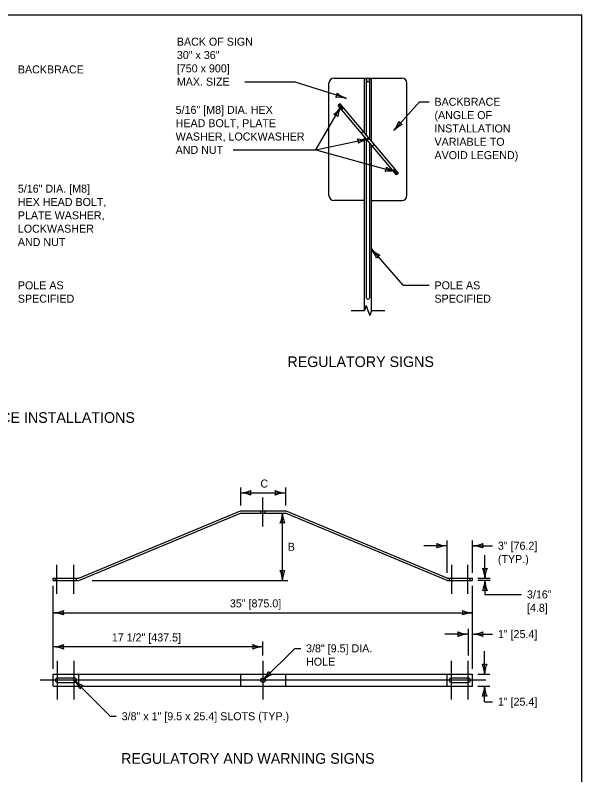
# Model space of a CAD drawing. Extents: x 49991.4 to 50021, y 49987.6 to 50011.4.
# Drawn here: x 50004.36 to 50008.61, y 50005.57 to 50011.26 of the extents above; entities that cross this region are included whole.
import ezdxf

# ---------------------------------------------------------------- set-up
doc = ezdxf.new("R2010")
doc.units = 0
for name, color, linetype in [('Level 1', 7, 'Continuous'), ('Level 2', 7, 'Continuous'), ('Level 3', 7, 'Continuous'), ('Level 4', 7, 'Continuous'), ('Level 5', 7, 'Continuous'), ('Level 6', 7, 'Continuous')]:
    doc.layers.add(name, color=color, linetype=linetype)

msp = doc.modelspace()

# ---------------------------------------------------------------- linework, layer by layer
at = {"layer": 'Level 1'}
for p, q in [((50006.7554, 50010.7907), (50007.264, 50010.7907)), ((50006.9838, 50010.7884), (50007.0356, 50010.7884)), ((50006.9838, 50010.3807), (50006.9838, 50010.7884)), ((50006.9961, 50010.7884), (50006.9961, 50010.3661)), ((50007.0231, 50010.3339), (50007.0231, 50010.7884)), ((50007.0356, 50010.319), (50007.0356, 50010.7884)), ((50006.7172, 50009.911), (50006.7172, 50010.7524)), ((50007.3023, 50009.911), (50007.3023, 50010.7524)), ((50006.8008, 50010.5988), (50006.786, 50010.5863)), ((50007.2382, 50010.0776), (50006.8008, 50010.5988)), ((50007.2232, 50010.0651), (50006.786, 50010.5863)), ((50006.7978, 50010.5827), (50006.8116, 50010.5663)), ((50006.8023, 50010.5865), (50006.816, 50010.5701)), ((50006.8274, 50010.5672), (50006.8126, 50010.5546)), ((50006.9754, 50010.3907), (50006.9605, 50010.3783)), ((50006.9838, 50009.0483), (50006.9838, 50010.3505)), ((50006.9962, 50010.3358), (50006.9962, 50009.1471)), ((50007.0232, 50009.1471), (50007.0232, 50010.3036)), ((50007.0356, 50009.0483), (50007.0356, 50010.2887)), ((50007.0583, 50010.292), (50007.0433, 50010.2795)), ((50007.2116, 50010.1092), (50007.1968, 50010.0968)), ((50007.2084, 50010.0938), (50007.2221, 50010.0774)), ((50007.2128, 50010.0975), (50007.2266, 50010.0811)), ((50007.2382, 50010.0776), (50007.2232, 50010.0651)), ((50006.9838, 50009.8727), (50006.7554, 50009.8727)), ((50007.0356, 50009.8727), (50007.264, 50009.8727)), ((50004.8399, 50007.0405), (50006.0533, 50007.546)), ((50004.8399, 50007.0236), (50006.0533, 50007.5292)), ((50006.0533, 50007.546), (50006.3903, 50007.546)), ((50006.0533, 50007.5292), (50006.3903, 50007.5292)), ((50007.6037, 50007.0405), (50006.3903, 50007.546)), ((50007.6037, 50007.0236), (50006.3903, 50007.5292)), ((50004.649, 50007.0236), (50004.649, 50007.0405)), ((50004.649, 50007.0405), (50004.8399, 50007.0405)), ((50004.649, 50007.0236), (50004.8399, 50007.0236)), ((50007.6037, 50007.0405), (50007.7947, 50007.0405)), ((50007.6037, 50007.0236), (50007.7947, 50007.0236)), ((50007.7947, 50007.0236), (50007.7947, 50007.0405)), ((50004.649, 50006.3213), (50007.7947, 50006.3213)), ((50004.649, 50006.2314), (50004.649, 50006.3213)), ((50004.8399, 50006.2314), (50004.8399, 50006.3213)), ((50006.0533, 50006.3213), (50006.0533, 50006.2314)), ((50006.3903, 50006.3213), (50006.3903, 50006.2314)), ((50007.6037, 50006.2314), (50007.6037, 50006.3213)), ((50007.7947, 50006.2314), (50007.7947, 50006.3213)), ((50004.6813, 50006.2932), (50004.8062, 50006.2932)), ((50007.6375, 50006.2933), (50007.7611, 50006.2933)), ((50004.649, 50006.2314), (50007.7947, 50006.2314)), ((50004.6813, 50006.2592), (50004.8062, 50006.2592)), ((50007.6375, 50006.2593), (50007.7611, 50006.2593))]:
    msp.add_line(p, q, dxfattribs=at)
msp.add_lwpolyline([(50008.6146, 50011.2628), (50000.3356, 50011.2628), (50000.3356, 50000.0624), (50008.6146, 50000.0624)], close=True, dxfattribs=at)
for centre, radius in [((50007.0095, 50010.7654), 0.00425), ((50007.0097, 50010.3348), 0.0051), ((50006.2218, 50006.2763), 0.0169)]:
    msp.add_circle(centre, radius, dxfattribs=at)
for centre, radius, start, end in [((50006.7554, 50010.7524), 0.0383, 90, 180), ((50007.264, 50010.7524), 0.0383, 0, 90), ((50006.8001, 50010.5846), 0.00292, 39.9351, 219.9351), ((50006.8138, 50010.5682), 0.00292, 220, 40), ((50007.2106, 50010.0957), 0.00292, 39.9351, 219.9351), ((50007.2243, 50010.0793), 0.00292, 220, 40), ((50006.7554, 50009.911), 0.0383, 180, 270), ((50007.264, 50009.911), 0.0383, 270, 360), ((50007.0097, 50009.1471), 0.0135, 180, 0.0087), ((50004.6813, 50006.2762), 0.017, 90, 270), ((50004.8062, 50006.2762), 0.017, 270, 90), ((50007.6375, 50006.2763), 0.017, 90, 270), ((50007.7611, 50006.2763), 0.017, 270, 90)]:
    msp.add_arc(centre, radius, start, end, dxfattribs=at)
at = {"layer": 'Level 3'}
for p, q in [((50006.0858, 50010.7641), (50006.4564, 50010.7641)), ((50006.846, 50010.6394), (50006.4564, 50010.7641)), ((50007.3968, 50010.6135), (50007.2068, 50010.4001)), ((50007.3968, 50010.6135), (50007.469, 50010.6135)), ((50006.6192, 50010.253), (50006.8069, 50010.5764)), ((50006.6192, 50010.253), (50007.0097, 50010.3348)), ((50005.9982, 50010.253), (50006.6192, 50010.253)), ((50006.6192, 50010.253), (50007.2175, 50010.0875)), ((50007.2732, 50009.2372), (50007.0356, 50009.5099)), ((50007.2732, 50009.2372), (50007.469, 50009.2372)), ((50006.0533, 50007.7208), (50006.0533, 50007.586)), ((50006.3903, 50007.7208), (50006.3903, 50007.586)), ((50006.0533, 50007.6808), (50006.3903, 50007.6808)), ((50006.3678, 50007.0236), (50006.3678, 50007.5292)), ((50007.6037, 50007.0805), (50007.6037, 50007.3244)), ((50007.7947, 50007.0805), (50007.7947, 50007.3244)), ((50007.6037, 50007.2844), (50007.4303, 50007.2844)), ((50007.7947, 50007.2844), (50007.9447, 50007.2844)), ((50007.8878, 50007.0405), (50007.8878, 50007.2139)), ((50004.9399, 50007.0236), (50006.4078, 50007.0236)), ((50007.8347, 50007.0405), (50007.9278, 50007.0405)), ((50007.9278, 50007.0236), (50007.8347, 50007.0236)), ((50007.8878, 50007.0236), (50007.8878, 50006.9192)), ((50004.649, 50006.3613), (50004.649, 50006.9836)), ((50007.7947, 50006.3613), (50007.7947, 50006.9836)), ((50007.8878, 50006.9192), (50008.163, 50006.9192)), ((50004.649, 50006.7821), (50007.7947, 50006.7821)), ((50007.7611, 50006.6618), (50007.7611, 50006.4613)), ((50007.7611, 50006.6218), (50007.5877, 50006.6218)), ((50007.7947, 50006.6218), (50007.9447, 50006.6218)), ((50006.2218, 50006.4613), (50006.2218, 50006.5667)), ((50006.2218, 50006.5267), (50004.649, 50006.5267)), ((50006.2218, 50006.2763), (50006.4605, 50006.515)), ((50006.4605, 50006.515), (50006.5055, 50006.515)), ((50007.8851, 50006.3213), (50007.8851, 50006.4947)), ((50007.8347, 50006.3213), (50007.9251, 50006.3213)), ((50005.0767, 50006.0059), (50004.8063, 50006.2763)), ((50007.8347, 50006.2314), (50007.9251, 50006.2314)), ((50007.8851, 50006.1151), (50007.8851, 50006.2314)), ((50007.8851, 50006.1151), (50007.9447, 50006.1151)), ((50005.0767, 50006.0059), (50005.1217, 50006.0059))]:
    msp.add_line(p, q, dxfattribs=at)
for centre, radius, start, end in [((50006.7239, 50010.6785), 0.0548, 324.3929, 0.1153), ((50006.786, 50010.4142), 0.233, 75.0814, 94.3313), ((50006.9224, 50010.8481), 0.2223, 229.7101, 249.8936), ((50006.6194, 50010.6958), 0.2223, 307.3305, 327.514), ((50007.014, 50010.4696), 0.233, 152.7018, 171.9516), ((50006.7426, 50010.4655), 0.0548, 42.0133, 77.7356), ((50007.0225, 50010.5434), 0.233, 321.1427, 340.3926), ((50007.3638, 50010.2427), 0.2223, 115.7714, 135.9549), ((50007.2892, 50010.493), 0.0548, 210.4542, 246.1766), ((50006.9731, 50010.5541), 0.2223, 259.297, 279.4805), ((50006.8842, 50010.3085), 0.0548, 353.9798, 29.7022), ((50007.0687, 50010.1094), 0.233, 104.6683, 123.9182), ((50007.0939, 50010.1217), 0.0548, 326.6751, 2.3974), ((50007.1665, 50009.8601), 0.233, 77.3636, 96.6134), ((50007.2855, 50010.2991), 0.2223, 231.9923, 252.1758), ((50006.8621, 50009.3709), 0.2223, 18.5212, 38.7047), ((50007.2035, 50009.6714), 0.233, 223.8925, 243.1424), ((50007.1198, 50009.4132), 0.0548, 113.204, 148.9264), ((50006.0418, 50007.9135), 0.233, 272.8273, 292.0772), ((50006.1815, 50007.6808), 0.0548, 162.1388, 197.8612), ((50006.3995, 50007.9029), 0.2223, 247.456, 267.6395), ((50006.2621, 50007.6808), 0.0548, 342.1388, 17.8612), ((50006.0441, 50007.4587), 0.2223, 67.456, 87.6395), ((50006.4018, 50007.4481), 0.233, 92.8273, 112.0772), ((50006.1457, 50007.5384), 0.2223, 337.456, 357.6395), ((50006.6005, 50007.5407), 0.233, 182.8273, 202.0772), ((50006.3678, 50007.401), 0.0548, 72.1388, 107.8612), ((50007.6129, 50007.5065), 0.2223, 247.456, 267.6395), ((50007.4755, 50007.2844), 0.0548, 342.1388, 17.8612), ((50007.7832, 50007.5171), 0.233, 272.8273, 292.0772), ((50007.9229, 50007.2844), 0.0548, 162.1388, 197.8612), ((50007.6152, 50007.0517), 0.233, 92.8273, 112.0772), ((50007.7855, 50007.0623), 0.2223, 67.456, 87.6395), ((50007.8878, 50007.1687), 0.0548, 252.1388, 287.8612), ((50007.6551, 50007.029), 0.233, 2.8273, 22.0772), ((50008.1099, 50007.0313), 0.2223, 157.456, 177.6395), ((50006.3678, 50007.1518), 0.0548, 252.1388, 287.8612), ((50006.1351, 50007.0121), 0.233, 2.8273, 22.0772), ((50006.5899, 50007.0144), 0.2223, 157.456, 177.6395), ((50007.6657, 50007.0328), 0.2223, 337.456, 357.6395), ((50008.1205, 50007.0351), 0.233, 182.8273, 202.0772), ((50007.8878, 50006.8954), 0.0548, 72.1388, 107.8612), ((50004.6375, 50007.0148), 0.233, 272.8273, 292.0772), ((50004.6398, 50006.56), 0.2223, 67.456, 87.6395), ((50004.7772, 50006.7821), 0.0548, 162.1388, 197.8612), ((50007.8039, 50007.0042), 0.2223, 247.456, 267.6395), ((50007.6665, 50006.7821), 0.0548, 342.1388, 17.8612), ((50007.8062, 50006.5494), 0.233, 92.8273, 112.0772), ((50007.7703, 50006.844), 0.2223, 247.456, 267.6395), ((50007.6329, 50006.6218), 0.0548, 342.1388, 17.8612), ((50007.7726, 50006.3891), 0.233, 92.8273, 112.0772), ((50007.7832, 50006.8546), 0.233, 272.8273, 292.0772), ((50007.7855, 50006.3997), 0.2223, 67.456, 87.6395), ((50007.9229, 50006.6218), 0.0548, 162.1388, 197.8612), ((50004.6375, 50006.7594), 0.233, 272.8273, 292.0772), ((50004.6398, 50006.3046), 0.2223, 67.456, 87.6395), ((50004.7772, 50006.5267), 0.0548, 162.1388, 197.8612), ((50006.231, 50006.7488), 0.2223, 247.456, 267.6395), ((50006.0936, 50006.5267), 0.0548, 342.1388, 17.8612), ((50006.2333, 50006.294), 0.233, 92.8273, 112.0772), ((50007.8851, 50006.4495), 0.0548, 252.1388, 287.8612), ((50007.6524, 50006.3098), 0.233, 2.8273, 22.0772), ((50008.1072, 50006.3121), 0.2223, 157.456, 177.6395), ((50006.0491, 50006.4327), 0.233, 317.8273, 337.0772), ((50006.3724, 50006.1128), 0.2223, 112.456, 132.6395), ((50006.3125, 50006.367), 0.0548, 207.1388, 242.8612), ((50004.6428, 50006.1257), 0.2223, 22.456, 42.6395), ((50004.9627, 50006.449), 0.233, 227.8273, 247.0772), ((50004.897, 50006.1856), 0.0548, 117.1388, 152.8612), ((50007.663, 50006.2406), 0.2223, 337.456, 357.6395), ((50008.1178, 50006.2429), 0.233, 182.8273, 202.0772), ((50007.8851, 50006.1032), 0.0548, 72.1388, 107.8612)]:
    msp.add_arc(centre, radius, start, end, dxfattribs=at)
at = {"layer": 'Level 4'}
for p, q in [((50006.2049, 50007.5292), (50006.2049, 50007.546)), ((50006.2387, 50007.5292), (50006.2387, 50007.546)), ((50004.6658, 50007.0236), (50004.6658, 50007.0405)), ((50004.8231, 50007.0236), (50004.8231, 50007.0405)), ((50007.6206, 50007.0236), (50007.6206, 50007.0405)), ((50007.7779, 50007.0236), (50007.7779, 50007.0405))]:
    msp.add_line(p, q, dxfattribs=at)
at = {"layer": 'Level 5'}
for p, q in [((50006.2218, 50007.4292), (50006.2218, 50007.646)), ((50004.6765, 50006.9236), (50004.6765, 50007.1405)), ((50004.8019, 50006.9236), (50004.8019, 50007.1405)), ((50007.6395, 50006.9236), (50007.6395, 50007.1405)), ((50007.7605, 50006.9236), (50007.7605, 50007.1405)), ((50004.6813, 50006.1314), (50004.6813, 50006.4213)), ((50004.8062, 50006.1314), (50004.8062, 50006.4213)), ((50006.2218, 50006.4213), (50006.2218, 50006.1314)), ((50007.6375, 50006.1314), (50007.6375, 50006.4213)), ((50007.7611, 50006.1314), (50007.7611, 50006.4213)), ((50007.8947, 50006.2763), (50004.549, 50006.2763))]:
    msp.add_line(p, q, dxfattribs=at)
at = {"layer": 'Level 6'}
for p, q in [((50006.9967, 50009.0849), (50006.9838, 50009.0483)), ((50006.9967, 50009.0849), (50007.0097, 50009.0483)), ((50006.8838, 50009.0483), (50006.9838, 50009.0483)), ((50007.0097, 50009.0483), (50007.0227, 50009.0117)), ((50007.0356, 50009.0483), (50007.0227, 50009.0117)), ((50007.0356, 50009.0483), (50007.1356, 50009.0483))]:
    msp.add_line(p, q, dxfattribs=at)

# ---------------------------------------------------------------- texts
at = {"layer": 'Level 2'}
for s, height, p in [('BACK OF SIGN', 0.06, (50005.5758, 50011.0341)), ('30" x 36"', 0.06, (50005.5758, 50010.9341)), ('BACKBRACE', 0.06, (50004.3827, 50010.8263)), ('[750 x 900]', 0.06, (50005.5758, 50010.8341)), ('MAX. SIZE', 0.06, (50005.5758, 50010.7341)), ('BACKBRACE', 0.06, (50007.509, 50010.5835)), ('5/16" [M8] DIA. HEX', 0.06, (50005.5668, 50010.523)), ('(ANGLE OF', 0.06, (50007.509, 50010.4835)), ('HEAD BOLT, PLATE', 0.06, (50005.5668, 50010.423)), ('INSTALLATION', 0.06, (50007.509, 50010.3835)), ('WASHER, LOCKWASHER', 0.06, (50005.5668, 50010.323)), ('VARIABLE TO', 0.06, (50007.509, 50010.2835)), ('AND NUT', 0.06, (50005.5668, 50010.223)), ('AVOID LEGEND)', 0.06, (50007.509, 50010.1835)), ('5/16" DIA. [M8] ', 0.06, (50004.3827, 50009.932)), ('HEX HEAD BOLT, ', 0.06, (50004.3827, 50009.832)), ('PLATE WASHER, ', 0.06, (50004.3827, 50009.732)), ('LOCKWASHER ', 0.06, (50004.3827, 50009.632)), ('AND NUT', 0.06, (50004.3827, 50009.532)), ('POLE AS', 0.06, (50004.3827, 50009.2072)), ('POLE AS', 0.06, (50007.509, 50009.2072)), ('SPECIFIED', 0.06, (50004.3827, 50009.1072)), ('SPECIFIED', 0.06, (50007.509, 50009.1072)), ('REGULATORY SIGNS', 0.08, (50006.4052, 50008.6246)), ('STEEL BACKBRACE INSTALLATIONS', 0.08, (50003.3705, 50008.206)), ('C', 0.06, (50006.2032, 50007.7208)), ('B', 0.06, (50006.4078, 50007.2464)), ('3" [76.2]', 0.06, (50007.9847, 50007.2544)), ('(TYP.)', 0.06, (50007.9847, 50007.1544)), ('3/16"', 0.06, (50008.203, 50006.8892)), ('35" [875.0]', 0.06, (50005.9738, 50006.8221)), ('[4.8]', 0.06, (50008.203, 50006.7892)), ('17 1/2" [437.5]', 0.06, (50005.0879, 50006.5667)), ('1" [25.4]', 0.06, (50007.9847, 50006.5918)), ('3/8" [9.5] DIA.', 0.06, (50006.5455, 50006.485)), ('HOLE', 0.06, (50006.5455, 50006.385)), ('1" [25.4]', 0.06, (50007.9847, 50006.0851)), ('3/8" x 1" [9.5 x 25.4] SLOTS (TYP.)', 0.06, (50005.1617, 50005.9759)), ('REGULATORY AND WARNING SIGNS', 0.08, (50005.1573, 50005.6495))]:
    msp.add_text(s, height=height, dxfattribs=at).set_placement(p)

doc.saveas('drawing.dxf')
